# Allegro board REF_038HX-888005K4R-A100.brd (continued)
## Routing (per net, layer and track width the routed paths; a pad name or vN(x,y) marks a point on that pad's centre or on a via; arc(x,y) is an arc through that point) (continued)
D11214: length 268.7
  TOP w0.203: SITE2.133 193.61,223.23 187.86,228.98 177.55,228.98 v2(177.25,229.28)
  L03_SIGNAL w0.135: 193.5,299.04 193.5,302.01 220.7,329.2 220.7,341.06 231.52,351.88 231.52,377.7 235.18,381.35 238.44,381.35 242.13,385.04 242.13,389.18
  L03_SIGNAL w0.145: 193.5,299.04 193.77,298.77 v2(194.23,298.77) ; 242.13,389.18 D112.14
  L20_SIGNAL w0.135: 176.88,228.91 176.14,228.91 175.72,229.33 175.72,231.67 175.85,231.8 176.04,231.8 176.21,231.64 176.4,231.64 176.59,231.83 176.59,232.02 176.43,232.19 176.43,232.37 176.62,232.57 176.81,232.57 176.97,232.4 177.16,232.4 177.36,232.59 177.36,232.78 177.19,232.95 177.19,233.14 186.82,242.77 186.82,251.17 198.41,262.76 198.41,265.76 203.13,270.48 203.13,272.61 206.27,275.75 214.02,275.75 217.02,278.75 217.02,280.63 221.56,285.17 221.56,286.45 220.94,287.07 219.19,287.07 210.93,278.81 207.18,278.81 205.99,280.01 205.99,292.34 202.91,295.41 194.96,295.41 193.5,296.87 193.5,298.5
  L20_SIGNAL w0.145: v2(177.25,229.28) 176.88,228.91 ; 193.5,298.5 193.77,298.77 v2(194.23,298.77)
D11215: length 268.7
  TOP w0.203: SITE2.141 189.29,220.03 187.06,222.26 180.84,222.26 v2(180.55,221.97)
  L05_SIGNAL w0.135: 193.09,254.67 193.09,253.82 193.6,253.31 195.15,253.31 197.59,255.76 197.59,301.73 214.15,318.29 214.15,378.44 234.46,398.75 242.69,398.75 244.3,397.14 244.3,395.66
  L05_SIGNAL w0.145: 193.09,254.67 192.83,254.94 v2(192.37,254.94) ; 244.3,395.66 243.53,394.89 242.76,394.89 D112.15
  L22_SIGNAL w0.135: 180.18,222.33 179.3,222.33 178.99,222.03 178.99,220.23 181.28,217.94 181.28,213.66 180.47,212.85 175.74,212.85 174.7,213.89 174.7,234.52 181.32,241.15 181.32,250.11 184.39,253.17 191.98,253.17 193.09,254.29 193.09,254.67
  L22_SIGNAL w0.145: v2(192.37,254.94) 192.83,254.94 193.09,254.67 ; v2(180.55,221.97) 180.18,222.33
D11216: length 268.7
  TOP w0.203: SITE2.134 193.24,222.83 187.63,228.43 177.55,228.43 v2(177.25,228.13)
  L03_SIGNAL w0.135: 193.09,299.04 193.09,302.18 220.29,329.37 220.29,341.23 231.11,352.05 231.11,377.86 235.01,381.76 238.27,381.76 241.72,385.21 241.72,389.29
  L03_SIGNAL w0.145: D112.16 240.21,389.98 241.03,389.98 241.72,389.29 ; v2(192.37,298.77) 192.83,298.77 193.09,299.04
  L20_SIGNAL w0.135: 193.09,298.5 193.09,296.7 194.79,295 202.74,295 205.58,292.17 205.58,279.84 207.01,278.41 211.1,278.41 219.36,286.66 220.77,286.66 221.15,286.28 221.15,285.34 216.61,280.8 216.61,278.92 213.85,276.16 206.1,276.16 202.72,272.78 202.72,270.65 198,265.93 198,262.93 186.41,251.34 186.41,242.93 175.31,231.84 175.31,229.16 175.97,228.5 176.88,228.5
  L20_SIGNAL w0.145: v2(192.37,298.77) 192.83,298.77 193.09,298.5 ; v2(177.25,228.13) 176.88,228.5
D11301: length 268.7
  TOP w0.203: v2(154.78,222.02) 154.48,222.32 146.16,222.32 144.27,220.43 SITE1.81
  L05_SIGNAL w0.135: 201.35,334.86 201.35,336.87 202.93,338.45 205.37,338.45 205.86,337.97 205.86,324.35 178.73,297.22 178.73,268.02 175.54,264.83 174.73,264.83 174.46,265.1 174.46,265.48
  L05_SIGNAL w0.145: 174.46,265.48 174.73,265.75 v2(175.19,265.75) ; D113.01 201.35,334.86
  L20_SIGNAL w0.135: 155.15,222.39 157.88,222.39 158.61,221.65 158.61,220.93 158.48,220.8 158.01,220.8 157.87,220.66 157.87,220.4 158.01,220.26 158.48,220.26 158.61,220.13 158.61,219.86 158.48,219.72 158.01,219.72 157.87,219.59 157.87,219.32 158.01,219.18 158.48,219.18 158.61,219.05 158.61,207.75 160.09,206.27 164.04,206.27 165.03,207.25 165.03,209.98 164.09,210.92 164.09,221.42 162.76,222.75 162.76,249.94 169.76,256.94 169.76,269.77 173.11,273.12 173.11,275.97 174.49,277.36 180,277.36 182.52,279.88 184.63,279.88 185.47,279.04 185.47,274.19 180.29,269.01 173.11,269.01 171.57,267.47 171.57,261.25 172.25,260.57 173.56,260.57 174.46,261.48 174.46,265.48
  L20_SIGNAL w0.145: v2(154.78,222.02) 155.15,222.39 ; 174.46,265.48 174.73,265.75 v2(175.19,265.75)
D11302: length 268.7
  TOP w0.203: v2(143.2,243.07) 142.91,242.77 142.91,238.16 140.65,235.9 140.65,233.11 134.92,227.38 SITE1.89
  L03_SIGNAL w0.135: 159.22,299.04 159.22,299.42 159.77,299.96 165.35,299.96 184.77,319.39 191.54,319.39 198.95,326.8 198.95,328.22
  L03_SIGNAL w0.145: 159.22,299.04 159.49,298.77 v2(159.95,298.77) ; 198.95,328.22 D113.02
  L20_SIGNAL w0.135: 142.84,243.43 142.84,244.15 143.58,244.89 143.77,244.89 143.95,244.72 144.14,244.72 144.33,244.91 144.33,245.1 144.15,245.27 144.15,245.46 150.44,251.75 156.08,251.75 157.01,252.68 157.01,261.33 157.5,261.82 158.95,261.82 159.54,261.24 159.54,257.92 160.01,257.44 161.41,257.44 161.96,258 161.96,291.17 162.45,291.66 163.45,291.66 163.85,291.26 163.85,275.58 164.74,274.69 166.44,274.69 166.97,275.22 166.97,292.58 171.84,297.45 171.84,299.92 173.03,301.11 176.96,301.11 178.22,299.85 178.22,288.96 179.44,287.74 182.37,287.74 184.37,289.75 184.37,302.09 182.83,303.63 169.69,303.63 169.12,303.06 169.12,298.99 165.89,295.76 159.69,295.76 159.22,296.22 159.22,298.5
  L20_SIGNAL w0.145: v2(159.95,298.77) 159.49,298.77 159.22,298.5 ; v2(143.2,243.07) 142.84,243.43
D11303: length 268.7
  TOP w0.203: v2(154.78,223.16) 154.48,222.87 145.93,222.87 143.9,220.83 SITE1.82
  L05_SIGNAL w0.135: 200.94,335.2 200.94,337.04 202.76,338.86 205.54,338.86 206.27,338.14 206.27,324.18 179.14,297.06 179.14,267.85 175.71,264.42 174.56,264.42 174.05,264.93 174.05,265.48
  L05_SIGNAL w0.145: D113.03 198.48,332.74 200.94,335.2 ; v2(173.33,265.75) 173.79,265.75 174.05,265.48
  L20_SIGNAL w0.135: 155.15,222.8 158.05,222.8 159.02,221.82 159.02,207.92 160.26,206.68 163.87,206.68 164.62,207.42 164.62,209.82 163.68,210.75 163.68,221.25 162.35,222.58 162.35,250.11 169.35,257.11 169.35,269.94 172.7,273.29 172.7,276.14 174.32,277.77 179.83,277.77 182.35,280.29 184.8,280.29 185.88,279.21 185.88,274.02 180.46,268.6 173.28,268.6 171.98,267.3 171.98,261.42 172.42,260.98 173.39,260.98 174.05,261.64 174.05,265.48
  L20_SIGNAL w0.145: 174.05,265.48 173.79,265.75 v2(173.33,265.75) ; v2(154.78,223.16) 155.15,222.8
D11304: length 268.7
  TOP w0.203: SITE1.90 134.52,227.76 140.1,233.34 140.1,236.13 142.36,238.39 142.36,242.77 v2(142.06,243.07)
  L03_SIGNAL w0.135: 158.81,299.04 158.81,299.59 159.6,300.37 165.18,300.37 184.6,319.8 191.37,319.8 198.54,326.97 198.54,328.33
  L03_SIGNAL w0.145: 198.54,328.33 197.85,329.03 197.02,329.03 D113.04 ; v2(158.09,298.77) 158.55,298.77 158.81,299.04
  L20_SIGNAL w0.135: 142.43,243.43 142.43,244.31 150.27,252.16 155.91,252.16 156.6,252.85 156.6,261.5 157.33,262.23 159.12,262.23 159.95,261.41 159.95,258.09 160.18,257.85 161.24,257.85 161.55,258.17 161.55,291.34 162.28,292.07 163.62,292.07 164.26,291.43 164.26,275.75 164.91,275.1 166.27,275.1 166.56,275.39 166.56,292.75 171.43,297.62 171.43,300.09 172.86,301.52 177.13,301.52 178.63,300.02 178.63,289.13 179.61,288.15 182.2,288.15 183.97,289.92 183.97,301.92 182.66,303.22 169.86,303.22 169.53,302.89 169.53,298.82 166.06,295.35 159.52,295.35 158.81,296.05 158.81,298.5
  L20_SIGNAL w0.145: v2(158.09,298.77) 158.55,298.77 158.81,298.5 ; v2(142.06,243.07) 142.43,243.43
D11305: length 268.7
  TOP w0.203: v2(151.73,220.09) 151.44,220.39 146.26,220.39 145.5,219.63 SITE1.79
  L05_SIGNAL w0.135: 174.46,254.67 174.46,254.29 174.73,254.02 175.87,254.02 186.59,264.74 186.59,300.89 208.31,322.61 208.31,341.25 207.13,342.42 193.53,342.42 191.07,339.96 191.07,334.98
  L05_SIGNAL w0.145: D113.05 191.07,334.98 ; 174.46,254.67 174.73,254.94 v2(175.19,254.94)
  L22_SIGNAL w0.135: 174.46,254.67 174.46,253.93 174.84,253.55 176.06,253.55 176.83,254.32 176.83,257.71 182.29,263.17 182.29,265.35 179.21,268.44 179.21,278.23 180.19,279.22 184.17,279.22 185.08,278.32 185.08,258.95 177.18,251.05 170.73,251.05 168.12,248.44 168.12,223.88 164.69,220.46 159.29,220.46 159.15,220.32 159.15,220.05 159.02,219.91 158.75,219.91 158.61,220.05 158.61,220.32 158.48,220.46 158.21,220.46 158.08,220.32 158.08,220.05 157.94,219.91 157.67,219.91 157.54,220.05 157.54,220.32 157.4,220.46 157.13,220.46 157,220.32 157,220.05 156.86,219.91 156.59,219.91 156.46,220.05 156.46,220.32 156.33,220.46 152.1,220.46
  L22_SIGNAL w0.145: v2(175.19,254.94) 174.73,254.94 174.46,254.67 ; 152.1,220.46 v2(151.73,220.09)
D11306: length 268.7
  TOP w0.203: SITE1.87 139.39,222.83 144.66,228.1 151.44,228.1 v2(151.73,227.81)
  L03_SIGNAL w0.135: 188.79,328.22 188.79,326.86 185.9,323.97 180.9,323.97 157.06,300.13 157.06,292.79 159.22,290.63 159.22,288.23
  L03_SIGNAL w0.145: v2(159.95,287.96) 159.49,287.96 159.22,288.23 ; 188.79,328.22 D113.06
  L22_SIGNAL w0.135: 152.1,228.17 153.03,228.17 153.58,228.73 153.86,228.73 154.1,228.97 154.1,229.25 158.27,233.42 158.27,248.55 164.11,254.39 164.11,283.11 169.32,288.33 169.32,322.81 168.59,323.55 166.82,323.55 166.16,322.88 166.16,303.23 165.66,302.73 164.65,302.73 164.07,303.31 164.07,323.03 163.55,323.55 161.71,323.55 161.01,322.84 161.01,286.96 160.59,286.55 159.49,286.55 159.22,286.82 159.22,287.69
  L22_SIGNAL w0.145: 159.22,287.69 159.49,287.96 v2(159.95,287.96) ; 152.1,228.17 v2(151.73,227.81)
D11307: length 268.7
  TOP w0.203: SITE1.80 145.12,220.03 146.03,220.94 151.44,220.94 v2(151.73,221.23)
  L05_SIGNAL w0.135: 190.66,334.91 190.66,340.13 193.36,342.83 207.3,342.83 208.72,341.42 208.72,322.44 187,300.72 187,264.57 176.03,253.61 174.56,253.61 174.06,254.12 174.06,254.67
  L05_SIGNAL w0.145: v2(173.33,254.94) 173.79,254.94 174.06,254.67 ; 190.66,334.91 190.04,334.29 189.78,334.29 D113.07
  L22_SIGNAL w0.135: 174.06,254.67 174.06,253.76 174.68,253.14 176.23,253.14 177.24,254.15 177.24,257.54 182.7,263 182.7,265.52 179.61,268.61 179.61,278.06 180.36,278.82 184,278.82 184.67,278.15 184.67,259.12 177.01,251.46 170.56,251.46 167.71,248.61 167.71,224.05 164.52,220.87 152.1,220.87
  L22_SIGNAL w0.145: 174.06,254.67 173.79,254.94 v2(173.33,254.94) ; 152.1,220.87 v2(151.73,221.23)
D11308: length 268.7
  TOP w0.203: v2(151.73,228.95) 151.44,228.65 144.44,228.65 139.01,223.23 SITE1.88
  L03_SIGNAL w0.135: 188.38,328.33 188.38,327.03 185.73,324.38 180.73,324.38 156.65,300.3 156.65,292.62 158.82,290.46 158.82,288.23
  L03_SIGNAL w0.145: D113.08 186.86,329.03 187.69,329.03 188.38,328.33 ; v2(158.09,287.96) 158.55,287.96 158.82,288.23
  L22_SIGNAL w0.135: 152.1,228.58 152.86,228.58 157.86,233.59 157.86,248.72 163.7,254.56 163.7,283.28 168.92,288.5 168.92,322.64 168.42,323.14 166.99,323.14 166.57,322.71 166.57,303.06 165.83,302.32 164.48,302.32 163.66,303.14 163.66,322.86 163.38,323.14 161.88,323.14 161.42,322.67 161.42,286.79 160.76,286.14 159.32,286.14 158.82,286.65 158.82,287.69
  L22_SIGNAL w0.145: 158.82,287.69 158.55,287.96 v2(158.09,287.96) ; 152.1,228.58 v2(151.73,228.95)
D11309: length 268.7
  TOP w0.203: v2(141.27,240.33) 140.98,240.03 140.98,238.29 139.28,236.6 139.28,233.36 134.12,228.2 SITE1.91
  L05_SIGNAL w0.135: 159.22,254.67 159.22,254.29 159.7,253.81 161.33,253.81 163.54,256.02 163.54,320.07 158.11,325.5 158.11,339.17 160.65,341.71 178.33,341.71 181.2,338.84 181.2,334.69
  L05_SIGNAL w0.145: v2(159.95,254.94) 159.49,254.94 159.22,254.67 ; D113.09 181.2,334.69
  L22_SIGNAL w0.135: 159.22,254.67 159.22,253.19 158.51,252.47 157.45,252.47 156.66,253.26 156.66,263.83 155.03,265.46 155.03,273.86 156.14,274.96 156.14,276.21 154.19,278.17 154.19,284.53 153.68,285.04 152.52,285.04 151.92,284.44 151.92,277.97 153.73,276.16 153.73,261.08 155.39,259.43 155.39,233.77 154.47,232.85 152.64,232.85 151.95,233.54 151.95,245.87 151.05,246.77 147.33,246.77 146.16,245.59 146.16,242.9 145.13,241.87 143.15,241.87 143.01,241.73 143.01,241.49 142.88,241.35 142.61,241.35 142.47,241.49 142.47,241.73 142.34,241.87 141.18,241.87 140.91,241.6 140.91,240.7
  L22_SIGNAL w0.145: 159.22,254.67 159.49,254.94 v2(159.95,254.94) ; 140.91,240.7 v2(141.27,240.33)
D11310: length 268.7
  TOP w0.203: v2(135.49,243.07) 135.19,242.77 135.19,238.91 134.32,238.04 134.32,234.11 131.32,231.12 SITE1.98
  L03_SIGNAL w0.135: 159.22,282.53 159.22,283.85 154.39,288.68 154.39,301.43 178.63,325.67 178.63,328.22
  L03_SIGNAL w0.145: v2(159.95,282.26) 159.49,282.26 159.22,282.53 ; 178.63,328.22 D113.10
  L20_SIGNAL w0.135: 135.12,243.43 135.12,244.49 135.25,244.63 135.5,244.63 135.64,244.76 135.64,245.03 135.5,245.17 135.25,245.17 135.12,245.3 135.12,246.12 141.58,252.59 141.58,256.72 148.95,264.08 148.95,293.41 152.51,296.98 152.51,303.06 152.98,303.53 161.68,303.53 165.33,307.18 165.33,319.78 165.69,320.15 167.02,320.15 167.44,319.72 167.44,311.58 168.15,310.88 169.33,310.88 169.91,311.45 169.91,319.79 170.31,320.19 171.69,320.19 172.02,319.86 172.02,309.48 163.11,300.57 157.57,300.57 156.32,299.33 156.32,273.43 157.03,272.72 158.69,272.72 159.22,273.25 159.22,281.99
  L20_SIGNAL w0.145: v2(159.95,282.26) 159.49,282.26 159.22,281.99 ; v2(135.49,243.07) 135.12,243.43
D11311: length 268.7
  TOP w0.203: SITE1.92 133.72,228.57 138.73,233.59 138.73,236.83 140.43,238.52 140.43,240.03 v2(140.13,240.33)
  L05_SIGNAL w0.135: 158.82,254.67 158.82,254.12 159.53,253.4 161.5,253.4 163.95,255.85 163.95,320.24 158.52,325.67 158.52,339 160.82,341.3 178.16,341.3 180.79,338.67 180.79,334.67
  L05_SIGNAL w0.145: D113.11 179.45,334.12 180.23,334.12 180.79,334.67 ; v2(158.09,254.94) 158.55,254.94 158.82,254.67
  L22_SIGNAL w0.135: 140.5,240.7 140.5,241.77 141.01,242.28 144.96,242.28 145.75,243.07 145.75,245.76 147.16,247.17 151.22,247.17 152.36,246.04 152.36,233.71 152.81,233.26 154.3,233.26 154.98,233.94 154.98,259.26 153.32,260.92 153.32,275.99 151.51,277.8 151.51,284.61 152.35,285.45 153.85,285.45 154.59,284.7 154.59,278.34 156.55,276.38 156.55,274.79 155.44,273.69 155.44,265.63 157.07,264 157.07,253.43 157.62,252.88 158.34,252.88 158.82,253.36 158.82,254.67
  L22_SIGNAL w0.145: v2(158.09,254.94) 158.55,254.94 158.82,254.67 ; 140.5,240.7 v2(140.13,240.33)
D11312: length 268.7
  TOP w0.203: v2(134.34,243.07) 134.64,242.77 134.64,239.13 133.77,238.26 133.77,234.34 130.92,231.49 SITE1.99
  L03_SIGNAL w0.135: 158.81,282.53 158.81,283.68 153.98,288.52 153.98,301.6 178.22,325.84 178.22,328.33
  L03_SIGNAL w0.145: 178.22,328.33 177.53,329.03 176.7,329.03 D113.12 ; v2(158.09,282.26) 158.55,282.26 158.81,282.53
  L20_SIGNAL w0.135: 158.81,281.99 158.81,273.42 158.52,273.13 157.2,273.13 156.73,273.6 156.73,299.16 157.74,300.16 163.27,300.16 172.43,309.31 172.43,320.03 171.86,320.6 170.14,320.6 169.5,319.95 169.5,311.62 169.16,311.28 168.32,311.28 167.85,311.75 167.85,319.89 167.19,320.55 165.52,320.55 164.92,319.95 164.92,307.35 161.51,303.94 152.81,303.94 152.1,303.23 152.1,297.14 148.54,293.58 148.54,264.25 141.17,256.89 141.17,252.76 134.71,246.29 134.71,243.43
  L20_SIGNAL w0.145: v2(158.09,282.26) 158.55,282.26 158.81,281.99 ; v2(134.34,243.07) 134.71,243.43
D11313: length 268.7
  TOP w0.203: v2(151.73,215.73) 151.44,216.03 145.58,216.03 144.38,217.23 SITE1.73
  L05_SIGNAL w0.135: 174.46,271.18 174.46,270.63 173.68,269.84 172.7,269.84 171.79,270.74 171.79,279.32 171.31,279.81 171.31,316.44 160.13,327.62 160.13,336.25 161.42,337.54 170.71,337.54 171.89,336.35 171.89,333.84
  L05_SIGNAL w0.145: 174.46,271.18 174.73,271.45 v2(175.19,271.45) ; D113.13 171.89,333.84
  L22_SIGNAL w0.135: 152.1,216.1 155.69,216.1 155.83,215.96 155.83,215.49 155.96,215.36 156.23,215.36 156.37,215.49 156.37,215.96 156.5,216.1 156.77,216.1 156.91,215.96 156.91,215.49 157.04,215.36 157.31,215.36 157.44,215.49 157.44,215.96 157.58,216.1 160.37,216.1 161.27,217 164.61,217 164.98,216.62 164.98,212.3 166.81,210.47 166.81,196.61 167.51,195.91 171.08,195.91 171.76,196.59 171.76,212.84 170.41,214.18 170.41,232.09 179.66,241.34 179.66,250.66 187.9,258.89 187.9,281.08 186.76,282.21 178.68,282.21 176.99,280.52 176.99,270.03 176.62,269.67 174.83,269.67 174.46,270.04 174.46,271.18
  L22_SIGNAL w0.145: v2(175.19,271.45) 174.73,271.45 174.46,271.18 ; 152.1,216.1 v2(151.73,215.73)
D11314: length 268.7
  TOP w0.203: SITE1.120 122.52,232.83 122.26,233.08 122.26,242.77 v2(122.56,243.07)
  L03_SIGNAL w0.135: v2(144.71,282.26) 144.25,282.26 143.98,282.53 143.98,283.59 148.77,288.37 148.77,301.51 168.39,321.13 168.39,328.14
  L03_SIGNAL w0.145: D113.14 168.39,328.14
  L20_SIGNAL w0.135: 143.98,281.99 143.98,274.31 141.46,271.79 141.46,268.16 140.82,267.52 139.33,267.52 138.57,268.27 138.57,273.76 141.32,276.51 141.32,280.13 138.91,282.54 138.91,297.64 143.87,302.6 143.87,311.17 143.61,311.42 142.5,311.42 142.04,310.97 142.04,303.11 141.12,302.19 139.54,302.19 138.91,302.81 138.91,310.95 138.49,311.37 137.03,311.37 136.55,310.89 136.55,301 136,300.46 134.43,300.46 133.8,301.09 133.8,311.04 133.46,311.38 131.95,311.38 131.3,310.73 131.3,254.74 129.12,252.55 124.2,252.55 122.19,250.55 122.19,246.76 122.33,246.62 122.4,246.62 122.53,246.49 122.53,246.22 122.4,246.08 122.33,246.08 122.19,245.95 122.19,245.68 122.33,245.55 122.4,245.55 122.53,245.41 122.53,245.14 122.4,245.01 122.33,245.01 122.19,244.87 122.19,243.43
  L20_SIGNAL w0.145: v2(122.56,243.07) 122.19,243.43 ; v2(144.71,282.26) 144.25,282.26 143.98,281.99
D11315: length 268.7
  TOP w0.203: v2(151.73,216.87) 151.44,216.58 145.81,216.58 144.75,217.63 SITE1.74
  L05_SIGNAL w0.135: 171.48,334.04 171.48,336.18 170.54,337.13 161.59,337.13 160.54,336.08 160.54,327.79 171.72,316.61 171.72,279.98 172.2,279.49 172.2,270.91 172.87,270.25 173.51,270.25 174.06,270.8 174.06,271.18
  L05_SIGNAL w0.145: v2(173.33,271.45) 173.79,271.45 174.06,271.18 ; 171.48,334.04 171.26,333.81 166.8,333.81 166.59,333.6 166.59,332.64 166.75,332.48 167.65,332.48 D113.15
  L22_SIGNAL w0.135: 174.06,271.18 174.06,269.87 174.66,269.26 176.79,269.26 177.4,269.86 177.4,280.36 178.84,281.8 186.6,281.8 187.49,280.91 187.49,259.06 179.25,250.83 179.25,241.51 170,232.26 170,214.01 171.35,212.67 171.35,196.76 170.91,196.32 167.68,196.32 167.22,196.78 167.22,210.64 165.39,212.47 165.39,216.79 164.78,217.4 161.1,217.4 160.2,216.51 152.1,216.51
  L22_SIGNAL w0.145: v2(173.33,271.45) 173.79,271.45 174.06,271.18 ; 152.1,216.51 v2(151.73,216.87)
D11316: length 268.7
  TOP w0.203: SITE1.121 122.12,232.45 121.72,232.85 121.72,242.77 v2(121.42,243.07)
  L03_SIGNAL w0.135: 167.98,328.32 167.98,321.3 148.36,301.68 148.36,288.54 143.57,283.76 143.57,282.53 143.31,282.26 v2(142.85,282.26)
  L03_SIGNAL w0.145: D113.16 166.54,329.03 167.27,329.03 167.98,328.32
  L20_SIGNAL w0.135: 121.79,243.43 121.79,250.72 124.03,252.96 128.95,252.96 130.89,254.91 130.89,310.9 131.78,311.79 133.63,311.79 134.21,311.21 134.21,301.26 134.6,300.87 135.83,300.87 136.14,301.17 136.14,311.06 136.86,311.78 138.66,311.78 139.32,311.12 139.32,302.98 139.71,302.6 140.95,302.6 141.63,303.28 141.63,311.14 142.33,311.83 143.78,311.83 144.28,311.34 144.28,302.43 139.32,297.47 139.32,282.71 141.73,280.3 141.73,276.34 138.98,273.59 138.98,268.44 139.5,267.93 140.65,267.93 141.05,268.33 141.05,271.96 143.57,274.48 143.57,281.99
  L20_SIGNAL w0.145: v2(142.85,282.26) 143.31,282.26 143.57,281.99 ; v2(121.42,243.07) 121.79,243.43
D11401: length 268.7
  TOP w0.203: SITE1.116 124.12,238.74 124.19,238.82 124.19,240.03 v2(124.49,240.33)
  L05_SIGNAL w0.135: 201.88,354.65 201.88,359.25 194.44,366.68 154.54,366.68 147.77,359.91 147.77,324.28 141.08,317.6 141.08,271.2 142.04,270.24 143.5,270.24 143.98,270.72 143.98,271.18
  L05_SIGNAL w0.145: D114.01 201.88,354.65 ; 143.98,271.18 144.25,271.45 v2(144.71,271.45)
  L22_SIGNAL w0.135: 143.98,271.18 143.98,270.12 143.31,269.45 141.93,269.45 140.5,270.88 140.5,276.64 135.61,281.53 132.18,281.53 131.06,280.42 125.4,280.42 124,279.01 124,274.98 125.05,273.93 131.79,273.93 132.88,272.84 132.88,269.28 131.03,267.43 126.97,267.43 126.23,266.69 126.23,264.73 126.93,264.03 128.58,264.03 132.88,259.72 132.88,252.92 124.12,244.15 124.12,242.39 124.26,242.25 124.51,242.25 124.64,242.12 124.64,241.85 124.51,241.72 124.26,241.72 124.12,241.58 124.12,240.7
  L22_SIGNAL w0.145: v2(144.71,271.45) 144.25,271.45 143.98,271.18 ; 124.12,240.7 v2(124.49,240.33)
D11402: length 268.7
  TOP w0.203: v2(131.63,243.07) 131.33,242.77 131.33,234.05 129.72,232.44 SITE1.102
  L03_SIGNAL w0.135: 198.98,348.57 198.98,342.36 194.15,337.53 152.35,337.53 148.18,333.35 148.18,324.11 143.98,319.92 143.98,299.04
  L03_SIGNAL w0.145: 198.98,348.57 D114.02 ; 143.98,299.04 144.25,298.77 v2(144.71,298.77)
  L20_SIGNAL w0.135: 143.98,298.5 143.98,297.56 144.35,297.19 145.23,297.19 146.07,298.04 146.07,324.82 147.42,326.17 161.53,326.17 163.03,324.67 163.03,308.6 160.13,305.7 150.45,305.7 149.64,304.89 149.64,297.96 146.7,295.02 146.7,265.03 138.05,256.38 138.05,253.99 131.26,247.2 131.26,245.54 131.39,245.41 131.64,245.41 131.78,245.27 131.78,245.01 131.64,244.87 131.39,244.87 131.26,244.74 131.26,243.43
  L20_SIGNAL w0.145: 143.98,298.5 144.25,298.77 v2(144.71,298.77) ; v2(131.63,243.07) 131.26,243.43
D11403: length 268.7
  TOP w0.203: v2(123.35,240.33) 123.65,240.03 123.65,238.81 123.72,238.74 SITE1.117
  L05_SIGNAL w0.135: 201.47,354.72 201.47,359.08 194.27,366.27 154.71,366.27 148.18,359.74 148.18,324.11 141.49,317.43 141.49,271.36 142.21,270.65 143.33,270.65 143.58,270.89 143.58,271.18
  L05_SIGNAL w0.145: 201.47,354.72 201.03,354.28 197.95,354.28 197.59,353.92 197.59,353.27 197.8,353.06 D114.03 ; v2(142.85,271.45) 143.31,271.45 143.58,271.18
  L22_SIGNAL w0.135: 143.58,271.18 143.58,270.29 143.14,269.86 142.1,269.86 140.91,271.05 140.91,276.81 135.78,281.94 132.01,281.94 130.89,280.83 125.23,280.83 123.59,279.18 123.59,274.81 124.88,273.52 131.63,273.52 132.48,272.67 132.48,269.45 130.87,267.84 126.8,267.84 125.82,266.86 125.82,264.56 126.76,263.62 128.41,263.62 132.48,259.55 132.48,253.08 123.72,244.32 123.72,240.7
  L22_SIGNAL w0.145: v2(142.85,271.45) 143.31,271.45 143.58,271.18 ; 123.72,240.7 v2(123.35,240.33)
D11404: length 268.7
  TOP w0.203: v2(130.48,243.07) 130.78,242.77 130.78,234.27 129.32,232.81 SITE1.103
  L03_SIGNAL w0.135: 198.57,348.59 198.57,342.53 193.98,337.94 152.18,337.94 147.77,333.52 147.77,324.28 143.57,320.09 143.57,299.04
  L03_SIGNAL w0.145: 143.57,299.04 143.31,298.77 v2(142.85,298.77) ; 198.57,348.59 197.81,349.35 197.02,349.35 D114.04
  L20_SIGNAL w0.135: 143.57,298.5 143.57,297.39 144.18,296.78 145.4,296.78 146.48,297.87 146.48,324.66 147.59,325.76 161.36,325.76 162.62,324.5 162.62,308.77 159.96,306.11 150.28,306.11 149.23,305.06 149.23,298.13 146.29,295.19 146.29,265.2 137.64,256.55 137.64,254.16 130.85,247.37 130.85,243.43
  L20_SIGNAL w0.145: 143.57,298.5 143.31,298.77 v2(142.85,298.77) ; v2(130.48,243.07) 130.85,243.43
D11405: length 268.7
  TOP w0.203: SITE1.112 125.72,236.89 128.05,239.22 128.05,240.03 v2(128.35,240.33)
  L05_SIGNAL w0.135: 191.39,354.98 191.39,357.62 185,364 155.64,364 150.44,358.8 150.44,323.73 146.02,319.3 146.02,310.93 147.22,309.73 147.22,255.74 145.5,254.02 144.25,254.02 143.98,254.29 143.98,254.67
  L05_SIGNAL w0.145: v2(144.71,254.94) 144.25,254.94 143.98,254.67 ; D114.05 191.39,354.98
  L22_SIGNAL w0.135: 143.98,254.67 143.98,254.12 141.95,252.09 139.94,252.09 138.52,253.5 138.52,275.68 136.62,277.57 127.88,277.57 127.47,277.17 127.47,276.49 127.88,276.08 135.02,276.08 136.54,274.57 136.54,252.27 127.98,243.71 127.98,242.51 128.12,242.38 128.36,242.38 128.5,242.24 128.5,241.97 128.36,241.84 128.12,241.84 127.98,241.7 127.98,240.7
  L22_SIGNAL w0.145: 127.98,240.7 v2(128.35,240.33) ; 143.98,254.67 144.25,254.94 v2(144.71,254.94)
D11406: length 268.7
  TOP w0.203: v2(133.56,240.33) 133.26,240.03 133.26,239.19 133.01,238.95 133.01,234.29 130.52,231.79 SITE1.100
  L03_SIGNAL w0.135: 143.98,288.23 143.98,289.66 139.23,294.42 139.23,318.32 145.83,324.92 145.83,334.33 151.38,339.88 184.4,339.88 188.8,344.27 188.8,348.55
  L03_SIGNAL w0.145: 143.98,288.23 144.25,287.96 v2(144.71,287.96) ; 188.8,348.55 D114.06
  L22_SIGNAL w0.135: 133.19,240.7 133.19,241.66 133.32,241.79 133.57,241.79 133.71,241.93 133.71,242.2 133.57,242.33 133.32,242.33 133.19,242.47 133.19,244.09 136.98,247.88 142.15,247.88 147.5,253.23 147.5,275.09 138.28,284.32 133.49,284.32 132.19,285.61 132.19,298.63 125.81,305.01 119.5,305.01 118.45,306.06 118.45,311.01 119.95,312.51 130.25,312.51 138.95,303.81 138.95,287.95 140.75,286.15 143.43,286.15 143.98,286.71 143.98,287.69
  L22_SIGNAL w0.145: v2(144.71,287.96) 144.25,287.96 143.98,287.69 ; 133.19,240.7 v2(133.56,240.33)
D11407: length 268.7
  TOP w0.203: v2(127.21,240.33) 127.5,240.03 127.5,239.45 125.32,237.26 SITE1.113
  L05_SIGNAL w0.135: 143.58,254.67 143.58,254.12 144.08,253.61 145.67,253.61 147.63,255.57 147.63,309.9 146.43,311.1 146.43,319.14 150.85,323.56 150.85,358.63 155.81,363.6 184.83,363.6 190.98,357.45 190.98,355.07
  L05_SIGNAL w0.145: 143.58,254.67 143.31,254.94 v2(142.85,254.94) ; 190.98,355.07 190.27,354.36 189.53,354.36 D114.07
  L22_SIGNAL w0.135: 143.58,254.67 143.58,254.29 141.78,252.5 140.1,252.5 138.93,253.67 138.93,275.85 136.79,277.98 127.71,277.98 127.06,277.34 127.06,276.32 127.71,275.67 134.85,275.67 136.13,274.4 136.13,252.44 127.57,243.88 127.57,240.7
  L22_SIGNAL w0.145: 127.57,240.7 v2(127.21,240.33) ; v2(142.85,254.94) 143.31,254.94 143.58,254.67
D11408: length 268.7
  TOP w0.203: SITE1.101 130.12,232.17 132.46,234.51 132.46,239.18 132.71,239.42 132.71,240.03 v2(132.41,240.33)
  L03_SIGNAL w0.135: 143.58,288.23 143.58,289.49 138.82,294.25 138.82,318.49 145.42,325.09 145.42,334.5 151.21,340.29 184.23,340.29 188.39,344.44 188.39,348.64
  L03_SIGNAL w0.145: D114.08 186.86,349.35 187.68,349.35 188.39,348.64 ; v2(142.85,287.96) 143.31,287.96 143.58,288.23
  L22_SIGNAL w0.135: 132.78,240.7 132.78,244.26 136.81,248.29 141.98,248.29 147.09,253.4 147.09,274.93 138.11,283.91 133.32,283.91 131.78,285.44 131.78,298.47 125.64,304.6 119.33,304.6 118.04,305.89 118.04,311.18 119.78,312.92 130.42,312.92 139.36,303.98 139.36,288.12 140.92,286.56 143.26,286.56 143.57,286.88 143.58,287.69
  L22_SIGNAL w0.145: 143.58,287.69 143.31,287.96 v2(142.85,287.96) ; 132.78,240.7 v2(132.41,240.33)
D11409: length 268.7
  TOP w0.203: SITE1.93 133.32,229.13 137.8,233.61 137.8,237.19 139.05,238.44 139.05,242.77 v2(139.34,243.07)
  L05_SIGNAL w0.135: 181.38,354.83 181.38,356.46 176.79,361.06 156.87,361.06 153.39,357.58 153.39,323.59 148.59,318.79 148.59,312.67 153.88,307.38 153.88,266.74 156.42,264.19 158.49,264.19 159.22,264.93 159.22,265.48
  L05_SIGNAL w0.145: 159.22,265.48 159.49,265.75 v2(159.95,265.75) ; D114.09 181.38,354.83
  L20_SIGNAL w0.135: 159.22,265.48 159.22,264.64 158.51,263.93 155.39,263.93 153.86,265.46 153.86,292.82 153.31,293.37 152.5,293.37 151.76,292.63 151.76,263.83 154.37,261.22 154.37,254.64 153.75,254.02 151.97,254.02 151.37,254.62 151.37,259.65 151.02,260 147.88,260 147.12,259.24 147.12,252.82 140.07,245.76 140.07,245.57 140.24,245.39 140.24,245.2 140.05,245.01 139.86,245.01 139.69,245.19 139.5,245.19 138.98,244.67 138.98,243.43
  L20_SIGNAL w0.145: v2(159.95,265.75) 159.49,265.75 159.22,265.48 ; v2(139.34,243.07) 138.98,243.43
D11410: length 268.7
  TOP w0.203: SITE1.133 113.61,223.23 107.86,228.98 97.55,228.98 v2(97.25,229.28)
  L03_SIGNAL w0.135: 178.63,348.54 178.63,345.81 175.02,342.2 150.42,342.2 143.51,335.29 143.51,325.82 128.74,311.05 128.74,299.04
  L03_SIGNAL w0.145: 178.63,348.54 D114.10 ; v2(129.47,298.77) 129.01,298.77 128.74,299.04
  L20_SIGNAL w0.135: 96.88,228.91 95.89,228.91 95.62,229.18 95.62,231.5 96.1,231.98 96.29,231.98 96.46,231.81 96.65,231.81 96.84,232.01 96.84,232.2 96.67,232.36 96.67,232.55 96.86,232.74 97.05,232.74 97.22,232.58 97.41,232.58 97.6,232.77 97.6,232.96 97.44,233.13 97.44,233.32 106.77,242.65 106.77,249.28 104.33,251.71 104.33,268.12 104.87,268.65 106.97,268.65 107.34,268.28 107.34,251.83 108.05,251.12 109.4,251.12 110.01,251.73 110.01,271.13 116.66,277.78 116.66,299.54 113.18,303.02 113.18,307.09 114.37,308.27 123.84,308.27 124.78,307.34 124.78,297.03 125.72,296.09 128.02,296.09 128.74,296.82 128.74,298.5
  L20_SIGNAL w0.145: v2(129.47,298.77) 129.01,298.77 128.74,298.5 ; v2(97.25,229.28) 96.88,228.91
D11411: length 268.7
  TOP w0.203: v2(138.2,243.07) 138.5,242.77 138.5,238.66 137.25,237.42 137.25,233.84 132.92,229.51 SITE1.94
  L05_SIGNAL w0.135: 158.81,265.48 158.81,265.1 158.32,264.6 156.59,264.6 154.29,266.9 154.29,307.55 149,312.84 149,318.62 153.8,323.42 153.8,357.41 157.03,360.65 176.62,360.65 180.97,356.29 180.97,354.81
  L05_SIGNAL w0.145: 180.97,354.81 180.37,354.21 177.48,354.21 177.08,353.81 177.08,353.19 177.21,353.06 D114.11 ; 158.81,265.48 158.55,265.75 v2(158.09,265.75)
  L20_SIGNAL w0.135: 158.81,265.48 158.81,264.81 158.34,264.34 155.56,264.34 154.27,265.63 154.27,292.99 153.48,293.78 152.33,293.78 151.35,292.8 151.35,263.66 153.96,261.06 153.96,254.81 153.58,254.43 152.14,254.43 151.78,254.79 151.78,259.81 151.19,260.4 147.71,260.4 146.72,259.4 146.72,252.99 138.57,244.84 138.57,243.43
  L20_SIGNAL w0.145: v2(158.09,265.75) 158.55,265.75 158.81,265.48 ; v2(138.2,243.07) 138.57,243.43
D11412: length 268.7
  TOP w0.203: v2(97.25,228.13) 97.55,228.43 107.63,228.43 113.24,222.83 SITE1.134
  L03_SIGNAL w0.135: 128.33,299.04 128.33,311.22 143.1,325.99 143.1,335.46 150.25,342.61 174.85,342.61 178.22,345.98 178.22,348.65
  L03_SIGNAL w0.145: v2(127.61,298.77) 128.07,298.77 128.33,299.04 ; 178.22,348.65 177.53,349.35 176.7,349.35 D114.12
  L20_SIGNAL w0.135: 128.33,298.5 128.33,296.99 127.85,296.5 125.89,296.5 125.19,297.2 125.19,307.51 124.01,308.68 114.2,308.68 112.77,307.26 112.77,302.85 116.25,299.37 116.25,277.95 109.6,271.29 109.6,251.9 109.23,251.53 108.22,251.53 107.75,252 107.75,268.45 107.14,269.06 104.7,269.06 103.92,268.29 103.92,251.54 106.36,249.11 106.36,242.82 95.21,231.67 95.21,229.01 95.72,228.5 96.88,228.5
  L20_SIGNAL w0.145: 128.33,298.5 128.07,298.77 v2(127.61,298.77) ; v2(97.25,228.13) 96.88,228.5
D11413: length 268.7
  TOP w0.203: SITE1.95 132.52,229.94 136.33,233.75 136.33,238.1 137.12,238.88 137.12,240.03 v2(137.41,240.33)
  L05_SIGNAL w0.135: 171.73,354.32 171.73,356.82 169.95,358.6 157.88,358.6 155.84,356.56 155.84,323.53 159.25,320.13 159.25,309.41 156.47,306.63 156.47,270.93 157.41,269.98 158.58,269.98 159.22,270.63 159.22,271.18
  L05_SIGNAL w0.145: 159.22,271.18 159.49,271.45 v2(159.95,271.45) ; D114.13 171.73,354.32
  L22_SIGNAL w0.135: 159.22,271.18 159.22,270.08 158.66,269.52 157.41,269.52 156.66,270.28 156.66,272.11 158.91,274.36 158.91,278.43 156.26,281.08 156.26,309.04 154.46,310.83 149.3,310.83 147.46,308.99 147.46,278.22 152,273.67 152,252.23 148.44,248.67 146.57,248.67 142.72,244.82 137.8,244.82 137.05,244.07 137.05,242.58 137.18,242.45 137.43,242.45 137.56,242.31 137.56,242.04 137.43,241.91 137.18,241.91 137.05,241.77 137.05,240.7
  L22_SIGNAL w0.145: 137.05,240.7 v2(137.41,240.33) ; v2(159.95,271.45) 159.49,271.45 159.22,271.18
D11414: length 268.7
  TOP w0.203: SITE1.131 118.12,227.73 112.62,233.23 112.62,240.03 v2(112.91,240.33)
  L03_SIGNAL w0.135: 128.74,288.23 128.74,293.6 124,298.35 124,309.56 140.81,326.37 140.81,336.41 149.3,344.9 166.19,344.9 168.39,347.1 168.39,348.46
  L03_SIGNAL w0.145: 168.39,348.46 D114.14 ; 128.74,288.23 129.01,287.96 v2(129.47,287.96)
  L22_SIGNAL w0.135: 128.74,287.69 128.74,286.53 128.21,286 126.01,286 123.34,288.66 123.34,296.15 119.36,300.14 109.66,300.14 108.58,299.05 108.58,291.92 109.89,290.6 116.27,290.6 117.32,289.55 117.32,268.75 112.69,264.12 102.5,264.12 94.75,256.38 89.24,256.38 88.18,255.31 88.18,236.43 90.82,233.79 96.03,233.79 103.34,241.1 108.61,241.1 111.26,243.75 111.98,243.75 112.55,243.19 112.55,242.45 112.68,242.32 112.93,242.32 113.06,242.18 113.06,241.92 112.93,241.78 112.68,241.78 112.55,241.65 112.55,240.7
  L22_SIGNAL w0.145: v2(129.47,287.96) 129.01,287.96 128.74,287.69 ; 112.55,240.7 v2(112.91,240.33)
D11415: length 268.7
  TOP w0.203: v2(136.27,240.33) 136.57,240.03 136.57,239.11 135.79,238.32 135.79,233.98 132.12,230.31 SITE1.96
  L05_SIGNAL w0.135: 158.82,271.18 158.82,270.8 158.41,270.39 157.58,270.39 156.87,271.09 156.87,306.46 159.65,309.25 159.65,320.3 156.25,323.7 156.25,356.39 158.05,358.19 169.78,358.19 171.32,356.65 171.32,354.65
  L05_SIGNAL w0.145: D114.15 167.56,353.06 167.38,353.23 167.38,354.05 167.61,354.28 170.95,354.28 171.32,354.65 ; 158.82,271.18 158.55,271.45 v2(158.09,271.45)
  L22_SIGNAL w0.135: 136.64,240.7 136.64,244.24 137.63,245.23 142.55,245.23 146.4,249.08 148.27,249.08 151.59,252.4 151.59,273.5 147.05,278.05 147.05,309.16 149.13,311.24 154.63,311.24 156.67,309.21 156.67,281.25 159.31,278.6 159.31,274.19 157.07,271.94 157.07,270.45 157.58,269.93 158.49,269.93 158.82,270.25 158.82,271.18
  L22_SIGNAL w0.145: 158.82,271.18 158.55,271.45 v2(158.09,271.45) ; 136.64,240.7 v2(136.27,240.33)
D11416: length 268.7
  TOP w0.203: v2(111.77,240.33) 112.07,240.03 112.07,233 117.72,227.35 SITE1.132
  L03_SIGNAL w0.135: 167.98,348.64 167.98,347.27 166.02,345.31 149.13,345.31 140.4,336.58 140.4,326.54 123.59,309.73 123.59,298.18 128.34,293.43 128.34,288.23
  L03_SIGNAL w0.145: 167.98,348.64 167.27,349.35 166.54,349.35 D114.16 ; v2(127.61,287.96) 128.07,287.96 128.34,288.23
  L22_SIGNAL w0.135: 112.14,240.7 112.14,243.02 111.81,243.34 111.43,243.34 108.78,240.69 103.51,240.69 96.2,233.38 90.65,233.38 87.77,236.26 87.77,255.48 89.08,256.79 94.58,256.79 102.33,264.53 112.52,264.53 116.91,268.92 116.91,289.38 116.1,290.2 109.72,290.2 108.17,291.75 108.17,299.22 109.49,300.55 119.52,300.55 123.75,296.32 123.75,288.83 126.18,286.41 128.05,286.41 128.34,286.7 128.34,287.69
  L22_SIGNAL w0.145: v2(127.61,287.96) 128.07,287.96 128.34,287.69 ; 112.14,240.7 v2(111.77,240.33)
D11501: length 268.7
  TOP w0.203: SITE1.124 120.92,230.78 118.41,233.29 118.41,242.77 v2(118.7,243.07)
  L05_SIGNAL w0.135: 202.08,374.77 202.08,380.31 196.09,386.3 152.65,386.3 137.73,371.37 137.73,327.44 123.57,313.28 123.57,266.44 125.61,264.4 128.22,264.4 128.74,264.93 128.74,265.48
  L05_SIGNAL w0.145: D115.01 202.08,374.77 ; 128.74,265.48 129.01,265.75 v2(129.47,265.75)
  L20_SIGNAL w0.135: 118.34,243.43 118.34,244.8 118.47,244.93 118.72,244.93 118.85,245.07 118.85,245.34 118.72,245.47 118.47,245.47 118.34,245.61 118.34,255.65 119.03,256.35 122.93,256.35 123.99,257.4 123.99,266.79 124.43,267.23 125.43,267.23 125.9,266.75 125.9,258.14 126.53,257.51 128.13,257.51 128.74,258.13 128.74,265.48
  L20_SIGNAL w0.145: v2(118.7,243.07) 118.34,243.43 ; v2(129.47,265.75) 129.01,265.75 128.74,265.48
D11502: length 268.7
  TOP w0.203: v2(154.78,217.66) 154.48,217.96 146.11,217.96 146.04,218.03 SITE1.75
  L03_SIGNAL w0.135: 174.46,282.53 174.46,283.41 176.25,285.2 182.89,285.2 186.43,288.74 186.43,299.17 211.94,324.67 211.94,360.84 206.65,366.12 199.74,366.12 199.33,366.54 199.33,369.24
  L03_SIGNAL w0.145: 199.33,369.24 D115.02 ; v2(175.19,282.26) 174.73,282.26 174.46,282.53
  L20_SIGNAL w0.135: 155.15,218.03 155.91,218.03 156.25,217.69 156.25,213.42 156.11,213.29 155.64,213.29 155.51,213.15 155.51,212.88 155.64,212.75 156.11,212.75 156.25,212.62 156.25,212.35 156.11,212.21 155.64,212.21 155.51,212.08 155.51,211.81 155.64,211.67 156.11,211.67 156.25,211.54 156.25,206.85 158.68,204.43 166.18,204.43 167.81,206.06 167.81,208.78 168.41,209.37 168.41,221.03 165.34,224.1 165.34,245.93 171.75,252.34 171.75,255.1 177.87,261.22 177.87,262.9 188.79,273.82 188.79,281.84 188.17,282.47 179.84,282.47 177.54,280.17 174.95,280.17 174.46,280.65 174.46,281.99
  L20_SIGNAL w0.145: 174.46,281.99 174.73,282.26 v2(175.19,282.26) ; v2(154.78,217.66) 155.15,218.03
D11503: length 268.7
  TOP w0.203: v2(117.56,243.07) 117.86,242.77 117.86,233.06 120.52,230.4 SITE1.125
  L05_SIGNAL w0.135: 128.33,265.48 128.33,265.1 128.05,264.81 125.78,264.81 123.98,266.61 123.98,313.11 138.14,327.27 138.14,371.2 152.82,385.89 195.92,385.89 201.67,380.14 201.67,375.15
  L05_SIGNAL w0.145: D115.03 198.07,373.38 197.77,373.68 197.77,374.46 198.19,374.89 201.41,374.89 201.67,375.15 ; v2(127.61,265.75) 128.07,265.75 128.33,265.48
  L20_SIGNAL w0.135: 117.93,243.43 117.93,255.82 118.86,256.75 122.76,256.75 123.58,257.57 123.58,266.96 124.26,267.64 125.6,267.64 126.31,266.92 126.31,258.3 126.69,257.92 127.96,257.92 128.33,258.3 128.33,265.48
  L20_SIGNAL w0.145: 128.33,265.48 128.07,265.75 v2(127.61,265.75) ; v2(117.56,243.07) 117.93,243.43
D11504: length 268.7
  TOP w0.203: v2(154.78,218.8) 154.48,218.5 146.15,218.5 146.08,218.43 SITE1.76
  L03_SIGNAL w0.135: 174.05,282.53 174.05,283.58 176.08,285.6 182.72,285.6 186.02,288.91 186.02,299.34 211.53,324.84 211.53,360.67 206.48,365.71 199.58,365.71 198.92,366.37 198.92,369.25
  L03_SIGNAL w0.145: 198.92,369.25 198.69,369.49 195.64,369.49 195.26,369.86 195.26,370.47 195.64,370.84 D115.04 ; 174.05,282.53 173.79,282.26 v2(173.33,282.26)
  L20_SIGNAL w0.135: 155.15,218.43 156.08,218.43 156.66,217.86 156.66,207.02 158.84,204.83 166.01,204.83 167.4,206.23 167.4,208.94 168,209.54 168,220.86 164.93,223.93 164.93,246.1 171.34,252.51 171.34,255.27 177.46,261.39 177.46,263.07 188.38,273.99 188.38,281.67 188,282.06 180.01,282.06 177.71,279.76 174.78,279.76 174.05,280.48 174.05,281.99
  L20_SIGNAL w0.145: v2(154.78,218.8) 155.15,218.43 ; 174.05,281.99 173.79,282.26 v2(173.33,282.26)
D11505: length 268.7
  TOP w0.203: v2(116.77,240.33) 116.48,240.03 116.48,233.26 120.12,229.62 SITE1.126
  L05_SIGNAL w0.135: 128.74,271.18 128.74,270.82 128.24,270.32 126.81,270.32 125.89,271.24 125.89,312.02 140.4,326.54 140.4,370.26 153.76,383.62 187.9,383.62 191.97,379.56 191.97,374.72
  L05_SIGNAL w0.145: D115.05 191.97,374.72 ; 128.74,271.18 129.01,271.45 v2(129.47,271.45)
  L22_SIGNAL w0.135: 128.74,271.18 128.74,270.23 128.2,269.69 122.47,269.69 114.06,261.28 103.97,261.28 96.67,253.98 94.67,253.98 94.05,253.35 94.05,251.83 94.43,251.44 98.27,251.44 99.71,250 99.71,246.84 100.52,246.03 115.55,246.03 116.41,245.18 116.41,242.55 116.54,242.41 116.79,242.41 116.92,242.28 116.92,242.01 116.79,241.87 116.54,241.87 116.41,241.74 116.41,240.7
  L22_SIGNAL w0.145: v2(116.77,240.33) 116.41,240.7 ; 128.74,271.18 129.01,271.45 v2(129.47,271.45)
D11506: length 268.7
  TOP w0.203: v2(151.73,223.95) 151.44,224.25 145.8,224.25 142.78,221.23 SITE1.83
  L03_SIGNAL w0.135: v2(175.19,287.96) 174.73,287.96 174.46,288.23 174.46,292.3 208.91,326.75 208.91,359.59 205.4,363.1 189.94,363.1 189.02,364.02 189.02,369.09
  L03_SIGNAL w0.145: D115.06 189.02,369.09
  L22_SIGNAL w0.135: 152.1,224.32 156.06,224.32 156.86,225.12 157.05,225.12 157.39,224.79 157.58,224.79 157.77,224.98 157.77,225.17 157.43,225.5 157.43,225.69 157.62,225.88 157.81,225.88 158.15,225.55 158.34,225.55 158.53,225.74 158.53,225.93 158.2,226.26 158.2,226.45 160.51,228.77 160.51,230.74 165.03,235.26 165.03,250.2 169.51,254.69 169.51,280.18 173.19,283.86 182.32,283.86 185.81,287.36 185.81,305.12 183.96,306.97 179.03,306.97 176.95,304.89 176.95,287.55 176.01,286.61 174.83,286.61 174.46,286.98 174.46,287.69
  L22_SIGNAL w0.145: 174.46,287.69 174.73,287.96 v2(175.19,287.96) ; 152.1,224.32 v2(151.73,223.95)
D11507: length 268.7
  TOP w0.203: v2(115.63,240.33) 115.93,240.03 115.93,233.04 119.72,229.25 SITE1.127
  L05_SIGNAL w0.135: 191.56,375 191.56,379.39 187.73,383.21 153.93,383.21 140.81,370.09 140.81,326.37 126.3,311.86 126.3,271.41 126.98,270.73 128.07,270.73 128.33,270.99 128.33,271.18
  L05_SIGNAL w0.145: 128.33,271.18 128.07,271.45 v2(127.61,271.45) ; 191.56,375 191.22,374.66 188,374.66 187.66,374.32 187.66,373.62 187.9,373.38 D115.07
  L22_SIGNAL w0.135: 128.34,271.18 128.34,270.4 128.03,270.09 122.3,270.09 113.89,261.69 103.8,261.69 96.5,254.39 94.5,254.39 93.64,253.52 93.64,251.66 94.26,251.03 98.1,251.03 99.3,249.83 99.3,246.67 100.35,245.62 115.38,245.62 116,245.01 116,240.7
  L22_SIGNAL w0.145: 128.34,271.18 128.07,271.45 v2(127.61,271.45) ; v2(115.63,240.33) 116,240.7
D11508: length 268.7
  TOP w0.203: SITE1.84 142.41,221.63 145.57,224.79 151.44,224.79 v2(151.73,225.09)
  L03_SIGNAL w0.135: 188.61,369.02 188.61,363.85 189.77,362.69 205.23,362.69 208.5,359.42 208.5,326.92 174.06,292.47 174.06,288.23 173.79,287.96 v2(173.33,287.96)
  L03_SIGNAL w0.145: 188.61,369.02 188.08,369.55 185.31,369.55 184.94,369.93 184.94,370.47 185.31,370.84 D115.08
  L22_SIGNAL w0.135: 174.06,287.69 174.06,286.81 174.66,286.21 176.18,286.21 177.35,287.38 177.35,304.72 179.2,306.56 183.79,306.56 185.4,304.95 185.4,287.53 182.15,284.27 173.02,284.27 169.1,280.35 169.1,254.86 164.62,250.37 164.62,235.43 160.1,230.91 160.1,228.94 155.89,224.72 152.1,224.72
  L22_SIGNAL w0.145: 174.06,287.69 173.79,287.96 v2(173.33,287.96) ; 152.1,224.72 v2(151.73,225.09)
D11509: length 268.7
  TOP w0.203: SITE1.122 121.72,231.79 120.34,233.17 120.34,240.03 v2(120.63,240.33)
  L05_SIGNAL w0.135: 128.74,254.67 128.74,254.29 129.19,253.85 130.86,253.85 132.68,255.67 132.68,315.57 143.1,325.99 143.1,369.14 154.88,380.92 178.66,380.92 181.07,378.52 181.07,375.46
  L05_SIGNAL w0.145: v2(129.47,254.94) 129.01,254.94 128.74,254.67 ; D115.09 181.07,375.46
  L22_SIGNAL w0.135: 120.27,240.7 120.27,241.66 120.4,241.79 120.65,241.79 120.78,241.93 120.78,242.2 120.65,242.33 120.4,242.33 120.27,242.47 120.27,248.19 119.31,249.14 115.46,249.14 113.24,251.36 102.86,251.36 102.4,251.82 102.4,255.35 104.44,257.39 116.94,257.39 117.32,257.01 117.32,252.87 118.11,252.08 121.83,252.08 122.48,252.73 122.48,260.09 123.11,260.72 124.76,260.72 125.31,260.17 125.31,254 126.33,252.98 127.72,252.98 128.74,254.01 128.74,254.67
  L22_SIGNAL w0.145: v2(129.47,254.94) 129.01,254.94 128.74,254.67 ; 120.27,240.7 v2(120.63,240.33)
D11510: length 268.7
  TOP w0.203: v2(154.78,225.88) 154.48,226.18 145.35,226.18 141.2,222.03 SITE1.85
  L03_SIGNAL w0.135: v2(175.19,298.77) 174.73,298.77 174.46,299.04 174.46,300.46 176.85,302.85 180.79,302.85 205.94,328 205.94,357.6 203.86,359.67 181.42,359.67 178.94,362.15 178.94,369.17
  L03_SIGNAL w0.145: D115.10 178.94,369.17
  L20_SIGNAL w0.135: 155.15,226.25 156.08,226.25 156.22,226.11 156.22,225.64 156.35,225.51 156.62,225.51 156.76,225.64 156.76,226.11 156.89,226.25 157.16,226.25 157.3,226.11 157.3,225.64 157.43,225.51 157.7,225.51 157.83,225.64 157.83,226.11 157.97,226.25 159.9,226.25 160.67,227.02 160.67,230.64 159.84,231.47 157.99,231.47 157.35,230.83 157.35,229.09 157.09,228.83 155.53,228.83 155.31,229.06 155.31,230.96 154.8,231.47 153.1,231.47 152.4,232.17 152.4,237.62 150.41,239.61 150.41,248.05 151.22,248.86 153.96,248.86 154.58,248.24 154.58,234.26 155.31,233.53 157.23,233.53 157.93,234.23 157.93,248.87 163.09,254.02 163.09,256.42 167.53,260.86 167.53,271.15 169.65,273.27 169.65,288.97 174.46,293.79 174.46,298.5
  L20_SIGNAL w0.145: v2(154.78,225.88) 155.15,226.25 ; 174.46,298.5 174.73,298.77 v2(175.19,298.77)
D11511: length 268.7
  TOP w0.203: SITE1.123 121.32,231.41 119.79,232.94 119.79,240.03 v2(119.49,240.33)
  L05_SIGNAL w0.135: 180.66,375.2 180.66,378.35 178.49,380.51 155.05,380.51 143.51,368.97 143.51,325.82 133.09,315.4 133.09,255.5 131.03,253.44 129.02,253.44 128.34,254.12 128.34,254.67
  L05_SIGNAL w0.145: v2(127.61,254.94) 128.07,254.94 128.34,254.67 ; 180.66,375.2 180.1,374.65 179.34,374.65 D115.11
  L22_SIGNAL w0.135: 119.86,240.7 119.86,248.02 119.14,248.74 115.29,248.74 113.07,250.95 102.69,250.95 101.99,251.66 101.99,255.52 104.27,257.8 117.11,257.8 117.73,257.18 117.73,253.04 118.28,252.49 121.66,252.49 122.07,252.9 122.07,260.26 122.94,261.13 124.93,261.13 125.72,260.34 125.72,254.17 126.5,253.39 127.55,253.39 128.34,254.18 128.34,254.67
  L22_SIGNAL w0.145: 128.34,254.67 128.07,254.94 v2(127.61,254.94) ; 119.86,240.7 v2(119.49,240.33)
D11512: length 268.7
  TOP w0.203: SITE1.86 140.82,222.43 145.12,226.72 154.48,226.72 v2(154.78,227.02)
  L03_SIGNAL w0.135: v2(173.33,298.77) 173.79,298.77 174.05,299.04 174.05,300.63 176.68,303.26 180.62,303.26 205.53,328.17 205.53,357.43 203.69,359.26 181.25,359.26 178.53,361.98 178.53,369.13
  L03_SIGNAL w0.145: D115.12 175.27,370.84 174.87,370.44 174.87,369.91 175.32,369.46 178.21,369.46 178.53,369.13
  L20_SIGNAL w0.135: 174.05,298.5 174.05,293.95 169.24,289.14 169.24,273.44 167.12,271.32 167.12,261.03 162.68,256.59 162.68,254.19 157.53,249.04 157.53,234.39 157.07,233.93 155.48,233.93 154.99,234.43 154.99,248.41 154.13,249.27 151.05,249.27 150,248.22 150,239.44 151.99,237.45 151.99,232 152.93,231.06 154.63,231.06 154.9,230.79 154.9,228.89 155.37,228.42 157.26,228.42 157.76,228.92 157.76,230.66 158.16,231.06 159.68,231.06 160.26,230.47 160.26,227.19 159.73,226.65 155.15,226.65
  L20_SIGNAL w0.145: 174.05,298.5 173.79,298.77 v2(173.33,298.77) ; v2(154.78,227.02) 155.15,226.65
D11513: length 268.7
  TOP w0.203: SITE1.114 124.92,237.85 126.12,239.06 126.12,242.77 v2(126.42,243.07)
  L05_SIGNAL w0.135: 171.71,374.66 171.71,376.63 169.74,378.6 155.84,378.6 145.42,368.18 145.42,325.09 138.82,318.49 138.82,266.23 140.89,264.16 143.39,264.16 143.98,264.75 143.98,265.48
  L05_SIGNAL w0.145: 143.98,265.48 144.25,265.75 v2(144.71,265.75) ; D115.13 171.71,374.66
  L20_SIGNAL w0.135: 143.98,265.48 143.98,264.93 143.11,264.05 139.62,264.05 136.24,267.42 136.24,295.38 136.48,295.61 136.48,297.75 135.89,298.33 134.05,298.33 133.39,297.67 133.39,253.71 126.05,246.37 126.05,245.4 126.19,245.27 126.44,245.27 126.57,245.13 126.57,244.86 126.44,244.73 126.19,244.73 126.05,244.59 126.05,243.43
  L20_SIGNAL w0.145: v2(126.42,243.07) 126.05,243.43 ; 143.98,265.48 144.25,265.75 v2(144.71,265.75)
D11514: length 268.7
  TOP w0.203: SITE1.129 118.92,228.97 114.55,233.34 114.55,242.77 v2(114.84,243.07)
  L03_SIGNAL w0.135: 128.74,282.53 128.74,283.08 121.5,290.32 121.5,310.64 138.14,327.27 138.14,338.26 161.15,361.27 165.5,361.27 168.39,364.16 168.39,368.78
  L03_SIGNAL w0.145: 128.74,282.53 129.01,282.26 v2(129.47,282.26) ; 168.39,368.78 D115.14
  L20_SIGNAL w0.135: 114.48,243.43 114.48,244.58 113.86,245.2 112.3,245.2 112.16,245.33 112.16,245.58 112.03,245.71 111.76,245.71 111.63,245.58 111.63,245.33 111.49,245.2 110.53,245.2 110.04,245.69 110.04,248.49 110.5,248.95 113.64,248.95 114.48,249.79 114.48,267.82 117.91,271.25 117.91,274.06 121.48,277.63 121.48,293.23 122.11,293.86 124.44,293.86 125.43,292.87 125.43,281.66 123.75,279.99 123.75,274.29 117.36,267.89 117.36,259.07 117.98,258.45 121.37,258.45 122.08,259.16 122.08,268.2 128.74,274.86 128.74,281.99
  L20_SIGNAL w0.145: v2(129.47,282.26) 129.01,282.26 128.74,281.99 ; v2(114.84,243.07) 114.48,243.43
D11515: length 268.7
  TOP w0.203: v2(125.28,243.07) 125.57,242.77 125.57,239.29 124.52,238.23 SITE1.115
  L05_SIGNAL w0.135: 143.57,265.48 143.57,264.92 143.22,264.57 141.06,264.57 139.23,266.4 139.23,318.32 145.83,324.92 145.83,368.01 156.01,378.19 169.57,378.19 171.3,376.46 171.3,374.77
  L05_SIGNAL w0.145: 171.3,374.77 171.05,374.52 167.61,374.52 167.4,374.3 167.4,373.6 167.62,373.38 D115.15 ; 143.57,265.48 143.31,265.75 v2(142.85,265.75)
  L20_SIGNAL w0.135: 125.64,243.43 125.64,246.54 132.98,253.88 132.98,297.84 133.88,298.74 136.06,298.74 136.88,297.92 136.88,295.44 136.65,295.21 136.65,267.59 139.79,264.46 142.94,264.46 143.57,265.1 143.57,265.48
  L20_SIGNAL w0.145: v2(125.28,243.07) 125.64,243.43 ; 143.57,265.48 143.31,265.75 v2(142.85,265.75)
D11516: length 268.7
  TOP w0.203: v2(113.7,243.07) 114,242.77 114,233.12 118.52,228.6 SITE1.130
  L03_SIGNAL w0.135: 128.33,282.53 128.33,282.91 121.09,290.15 121.09,310.81 137.73,327.44 137.73,338.43 160.98,361.68 165.33,361.68 167.98,364.33 167.98,368.96
  L03_SIGNAL w0.145: 128.33,282.53 128.07,282.26 v2(127.61,282.26) ; 167.98,368.96 167.27,369.67 166.54,369.67 D115.16
  L20_SIGNAL w0.135: 128.33,281.99 128.33,275.03 121.67,268.37 121.67,259.33 121.2,258.86 118.15,258.86 117.77,259.24 117.77,267.72 124.16,274.12 124.16,279.82 125.84,281.49 125.84,293.04 124.61,294.27 121.94,294.27 121.07,293.4 121.07,277.79 117.5,274.23 117.5,271.42 114.07,267.98 114.07,249.96 113.47,249.36 110.33,249.36 109.63,248.66 109.63,245.52 110.36,244.79 113.69,244.79 114.07,244.41 114.07,243.43
  L20_SIGNAL w0.145: v2(113.7,243.07) 114.07,243.43 ; v2(127.61,282.26) 128.07,282.26 128.33,281.99
D11601: length 220.5
  L07_SIGNAL w0.17: v1(105.06,248.48) 105.06,252.62 138.7,286.26 138.7,318.26 155.46,335.03 155.46,395.99 159.27,399.8 197.37,399.8 D116.01
D11602: length 188.9
  TOP w0.231: UT1.2 v1(148.57,244.22)
  L07_SIGNAL w0.17: D116.02 194.33,384.56 164.79,384.56 160.8,380.56 160.8,332.82 149.37,321.39 149.37,255.78 150.22,254.92 150.22,245.87 v1(148.57,244.22)
D11603: length 219.4
  L07_SIGNAL w0.17: v1(105.06,243.18) 106.05,244.17 106.05,252.53 139.46,285.94 139.46,317.95 156.23,334.71 156.23,395.67 159.59,399.03 193.06,399.03 D116.03
D11604: length 183.2
  TOP w0.231: UT1.1 v1(148.57,245.49)
  L07_SIGNAL w0.17: v1(148.57,245.49) 149.47,246.39 149.47,254.15 148.61,255.02 148.61,321.7 160.04,333.13 160.04,380.88 164.48,385.32 190.01,385.32 D116.04
D11605: length 225.8
  L07_SIGNAL w0.17: v1(128.23,222.59) 128.82,223.18 128.82,226.59 130.95,228.73 130.95,240.97 133.01,243.03 133.01,244.76 140.22,251.97 143.09,251.97 145.56,254.44 145.56,322.96 156.99,334.39 156.99,395.35 159.9,398.27 188.74,398.27 D116.05
D11606: length 210.4
  TOP w0.231: SITE1.77 136.09,218.83 v1(135.72,218.46)
  L07_SIGNAL w0.17: D116.06 185.69,386.08 164.16,386.08 159.27,381.19 159.27,333.45 147.84,322.02 147.84,253.49 144.57,250.22 144.57,241.32 139.99,236.74 139.99,230.09 135.72,225.82 v1(135.72,218.46)
D11607: length 218.7
  L07_SIGNAL w0.17: v1(129.43,222.59) 130.07,223.23 130.07,225.22 133.68,228.83 133.68,237.5 134.91,238.73 134.91,241.28 136.74,243.11 136.74,246.96 140.99,251.21 143.4,251.21 146.32,254.12 146.32,322.65 157.75,334.08 157.75,395.04 160.22,397.51 184.42,397.51 D116.07
D11608: length 203.6
  L07_SIGNAL w0.17: D116.08 181.37,386.84 163.85,386.84 158.51,381.51 158.51,333.76 147.08,322.33 147.08,253.81 140.69,247.42 140.69,243.09 138.8,241.19 138.8,231.32 133.48,226 v1(133.48,219.47)
D11609: length 268.7
  TOP w0.203: SITE1.137 111.44,221.63 107.95,225.12 97.55,225.12 v2(97.25,225.42)
  L05_SIGNAL w0.135: 113.5,281.99 113.5,280.92 112.99,280.41 111.97,280.41 110.42,281.96 110.42,305.86 131.91,327.35 131.91,378.62 155.32,402.03 175.93,402.03 181.68,396.28 181.68,395.17
  L05_SIGNAL w0.145: v2(114.23,282.26) 113.77,282.26 113.5,281.99 ; D116.09 181.68,395.17
  L20_SIGNAL w0.135: 113.5,281.99 113.5,280.49 98.61,265.59 98.61,240.55 92.01,233.95 92.01,225.61 92.57,225.05 93.81,225.05 93.94,225.19 93.94,225.42 94.07,225.56 94.34,225.56 94.48,225.42 94.48,225.19 94.61,225.05 94.88,225.05 95.02,225.19 95.02,225.42 95.15,225.56 95.42,225.56 95.56,225.42 95.56,225.19 95.69,225.05 96.88,225.05
  L20_SIGNAL w0.145: v2(97.25,225.42) 96.88,225.05 ; v2(114.23,282.26) 113.77,282.26 113.5,281.99
